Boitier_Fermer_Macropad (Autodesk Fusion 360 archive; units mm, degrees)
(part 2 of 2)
extrude "Extrusion20" add sketch "Esquisse6" profile of L6 L7 L8 L13 along normal blind 0.15
sketch "Esquisse7" plane through (0, -33.8138, 0) normal (0, 1, 0) x axis (-1, 0, 0)
  line L1 (51.5, 17.329) -> (51.5, 10.829)
  line L2 (40, 17.329) -> (51.5, 17.329)
  line L3 (40, 16.1066) -> (40, 17.329)
  line L4 (28, 16.1066) -> (40, 16.1066)
  line L5 (28, 17.329) -> (28, 16.1066)
  line L6 (-31.9217, 17.329) -> (28, 17.329)
  line L7 (-31.9217, 10.829) -> (-31.9217, 17.329)
  line L8 (51.5, 10.829) -> (-31.9217, 10.829)
  line L9 (29.5, 16.1066) -> (28, 16.1066)
  line L10 (29.5, 10.829) -> (29.5, 16.1066)
  line L11 (28, 10.829) -> (29.5, 10.829)
  line L12 (28, 16.1066) -> (28, 10.829)
  line L13 (38.5, 16.1066) -> (40, 16.1066)
  line L14 (38.5, 10.829) -> (38.5, 16.1066)
  line L15 (40, 10.829) -> (38.5, 10.829)
  line L16 (40, 16.1066) -> (40, 10.829)
  point P6 (28, 16.1066)
  point P10 (28, 16.1066)
  point P5 (40, 16.1066)
  point P14 (40, 16.1066)
  point P11 (29.5, 16.1066)
  point P15 (38.5, 16.1066)
  horizontal L9
  vertical L10
  horizontal L11
  vertical L12
  coincident P6 P10
  horizontal L13
  vertical L14
  horizontal L15
  vertical L16
  coincident P5 P14
  dimension "d115" distance P10 P11 = 1.5
  dimension "d116" distance P14 P15 = 1.5
extrude "Extrusion21" add sketch "Esquisse7" profile of L4 L8 L9 L10 L11 L12 L13 L14 L15 L16 along normal blind 62.447
revolve "Révolution1" AlongAngle 10
revolve "Révolution2" AlongAngle 10
sketch "Esquisse8" plane through (0, 28.6329, 0) normal (0, -1, 0) x axis (1, 0, 0)
  line L1 (-40, 16.1066) -> (-40, 10.829)
  line L2 (-38.5, 16.1066) -> (-40, 16.1066)
  line L3 (-38.5, 10.829) -> (-38.5, 16.1066)
  line L4 (-29.5, 10.829) -> (-38.5, 10.829)
  line L5 (-29.5, 16.1066) -> (-29.5, 10.829)
  line L6 (-28, 16.1066) -> (-29.5, 16.1066)
  line L7 (-28, 10.829) -> (-28, 16.1066)
  line L8 (54.6352, 10.829) -> (-28, 10.829)
  line L9 (54.6352, 27.384) -> (54.6352, 10.829)
  line L10 (-28, 27.384) -> (54.6352, 27.384)
  line L11 (-28, 27.1177) -> (-28, 27.384)
  line L12 (-40, 27.1177) -> (-28, 27.1177)
  line L13 (-40, 27.384) -> (-40, 27.1177)
  line L14 (-51.5, 27.384) -> (-40, 27.384)
  line L15 (-51.5, 10.829) -> (-51.5, 27.384)
  line L16 (-40, 10.829) -> (-51.5, 10.829)
  line L17 (-28, 26.9504) -> (-28, 16.1066)
  line L18 (-40, 26.9504) -> (-40, 16.1066)
  line L19 (-40, 27.1177) -> (-40, 26.9504)
  line L20 (-40, 27.384) -> (-40, 27.1177)
  line L21 (-38.5, 16.1066) -> (-40, 16.1066)
  line L22 (-38.5, 27.1177) -> (-38.5, 16.1066)
  line L23 (-40, 27.1177) -> (-38.5, 27.1177)
  line L24 (-40, 16.1066) -> (-40, 27.1177)
  line L25 (-28, 16.1066) -> (-29.5, 16.1066)
  line L26 (-28, 27.1177) -> (-28, 16.1066)
  line L27 (-29.5, 27.1177) -> (-28, 27.1177)
  line L28 (-29.5, 16.1066) -> (-29.5, 27.1177)
  point P26 (-38.5, 27.1177)
  point P20 (-40, 16.1066)
  point P24 (-40, 16.1066)
  point P13 (-28, 27.1177)
  point P30 (-28, 27.1177)
  point P7 (-29.5, 16.1066)
  point P28 (-29.5, 16.1066)
  point P25 (-38.5, 16.1066)
  horizontal L21
  vertical L22
  horizontal L23
  vertical L24
  coincident L12 P26
  coincident P20 P24
  horizontal L25
  vertical L26
  horizontal L27
  vertical L28
  coincident P13 P30
  coincident P7 P28
  dimension "d121" distance P24 P25 = 1.5
extrude "Extrusion22" add sketch "Esquisse8" profile of L2 L6 L12 L17 L18 L19 L21 L22 L23 L24 L25 L26 L27 L28 along normal blind 2
sketch "Esquisse1" plane through (0, 0, 10.829) normal (0, 0, -1) x axis (1, 0, 0)
  line L1 (-29.5, 33.8138) -> (-38.5, 33.8138)
  line L2 (-29.5, -28.6329) -> (-29.5, 33.8138)
  line L3 (-38.5, -28.6329) -> (-29.5, -28.6329)
  line L4 (-38.5, 33.8138) -> (-38.5, -28.6329)
  line L5 (-40, -28.6329) -> (-40, 33.8138)
  line L6 (-51.5, -28.6329) -> (-40, -28.6329)
  line L7 (-51.5, -24.5983) -> (-51.5, -28.6329)
  line L8 (-54, -22.1363) -> (-51.5, -24.5983)
  line L9 (-59.5673, -22.1363) -> (-54, -22.1363)
  line L10 (-59.5673, 25.627) -> (-59.5673, -22.1363)
  line L11 (-54, 25.627) -> (-59.5673, 25.627)
  line L12 (-51.5, 28.089) -> (-54, 25.627)
  line L13 (-51.5, 33.8138) -> (-51.5, 28.089)
  line L14 (-40, 33.8138) -> (-51.5, 33.8138)
  line L15 (31.9217, 33.8138) -> (-28, 33.8138)
  line L16 (34.6131, 29.5161) -> (31.9217, 33.8138)
  line L17 (52.9048, 29.5161) -> (34.6131, 29.5161)
  line L18 (54.6352, 32.6305) -> (52.9048, 29.5161)
  line L19 (54.6352, 28.6738) -> (54.6352, 32.6305)
  line L20 (53.7874, 27.1479) -> (54.6352, 28.6738)
  line L21 (54.6352, 25.627) -> (53.7874, 27.1479)
  line L22 (62.5975, 25.627) -> (54.6352, 25.627)
  line L23 (62.5975, -22.1363) -> (62.5975, 25.627)
  line L24 (57.1352, -22.1363) -> (62.5975, -22.1363)
  line L25 (54.6352, -24.5983) -> (57.1352, -22.1363)
  line L26 (54.6352, -28.6329) -> (54.6352, -24.5983)
  line L27 (-28, -28.6329) -> (54.6352, -28.6329)
  line L28 (-28, 33.8138) -> (-28, -28.6329)
  line L29 (61.6004, -30.3827) -> (-58.5552, -30.3827)
  line L30 (64.3975, -27.4794) -> (61.6004, -30.3827)
  line L31 (64.3975, 32.3196) -> (64.3975, -27.4794)
  line L32 (61.2304, 35.4386) -> (64.3975, 32.3196)
  line L33 (54.1497, 35.4386) -> (61.2304, 35.4386)
  line L34 (51.9955, 31.5614) -> (54.1497, 35.4386)
  line L35 (35.4395, 31.5614) -> (51.9955, 31.5614)
  line L36 (32.9332, 35.5637) -> (35.4395, 31.5614)
  line L37 (-58.5662, 35.5637) -> (32.9332, 35.5637)
  line L38 (-61.3673, 33.2697) -> (-58.5662, 35.5637)
  line L39 (-61.3673, -27.4752) -> (-61.3673, 33.2697)
  line L40 (-58.5552, -30.3827) -> (-61.3673, -27.4752)
  line L41 (-51.3, -28.4329) -> (-40.2, -28.4329)
  line L42 (-51.3, -24.5146) -> (-51.3, -28.4329)
  line L43 (-53.9181, -21.9363) -> (-51.3, -24.5146)
  line L44 (-59.3673, -21.9363) -> (-53.9181, -21.9363)
  line L45 (-59.3673, 25.427) -> (-59.3673, -21.9363)
  line L46 (-53.9181, 25.427) -> (-59.3673, 25.427)
  line L47 (-51.3, 28.0053) -> (-53.9181, 25.427)
  line L48 (-51.3, 33.6138) -> (-51.3, 28.0053)
  line L49 (-40.2, 33.6138) -> (-51.3, 33.6138)
  line L50 (-40.2, -28.4329) -> (-40.2, 33.6138)
  line L51 (62.3975, 25.427) -> (54.5177, 25.427)
  line L52 (62.3975, -21.9363) -> (62.3975, 25.427)
  line L53 (57.0533, -21.9363) -> (62.3975, -21.9363)
  line L54 (54.4352, -24.5146) -> (57.0533, -21.9363)
  line L55 (54.4352, -28.4329) -> (54.4352, -24.5146)
  line L56 (-27.8, -28.4329) -> (54.4352, -28.4329)
  line L57 (-27.8, 33.6138) -> (-27.8, -28.4329)
  line L58 (31.811, 33.6138) -> (-27.8, 33.6138)
  line L59 (34.5023, 29.3161) -> (31.811, 33.6138)
  line L60 (-48.52, -23.3506) -> (-48.52, -25.6529)
  line L61 (-52.779, -19.1563) -> (-48.52, -23.3506)
  line L62 (-56.5873, -19.1563) -> (-52.779, -19.1563)
  line L63 (-56.5873, 22.647) -> (-56.5873, -19.1563)
  line L64 (-52.779, 22.647) -> (-56.5873, 22.647)
  line L65 (-48.52, 26.8413) -> (-52.779, 22.647)
  line L66 (-48.52, 30.8338) -> (-48.52, 26.8413)
  line L67 (-42.98, 30.8338) -> (-48.52, 30.8338)
  line L68 (-42.98, -25.6529) -> (-42.98, 30.8338)
  line L69 (-48.52, -25.6529) -> (-42.98, -25.6529)
  line L70 (52.3496, 29.3161) -> (54.5177, 25.427)
  line L71 (34.5023, 29.3161) -> (52.3496, 29.3161)
  line L72 (52.8847, 22.647) -> (50.7166, 26.5361)
  line L73 (59.6175, 22.647) -> (52.8847, 22.647)
  line L74 (59.6175, -19.1563) -> (59.6175, 22.647)
  line L75 (55.9142, -19.1563) -> (59.6175, -19.1563)
  line L76 (51.6552, -23.3506) -> (55.9142, -19.1563)
  line L77 (51.6552, -25.6529) -> (51.6552, -23.3506)
  line L78 (-25.02, -25.6529) -> (51.6552, -25.6529)
  line L79 (-25.02, 30.8338) -> (-25.02, -25.6529)
  line L80 (30.2718, 30.8338) -> (-25.02, 30.8338)
  line L81 (32.9631, 26.5361) -> (30.2718, 30.8338)
  line L82 (50.7166, 26.5361) -> (32.9631, 26.5361)
  line L83 (-25.02, -28.4329) -> (-25.02, -25.6529)
  line L84 (-25.02, 33.6138) -> (-25.02, 30.8338)
  line L85 (-42.98, 33.6138) -> (-42.98, 30.8338)
  line L86 (-42.98, -28.4329) -> (-42.98, -25.6529)
  point P84 (-25.02, -28.4329)
  point P85 (-25.02, 33.6138)
  point P86 (-42.98, 33.6138)
  point P87 (-42.98, -28.4329)
  horizontal L71
  coincident L56 P84
  perpendicular L56 L83
  coincident L58 P85
  perpendicular L58 L84
  coincident L49 P86
  perpendicular L49 L85
  coincident L41 P87
  perpendicular L41 L86
  dimension "d124" = 0.2
  dimension "d125" = 0.2
  dimension "d126" = 2.98 (= "3 mm - 0.02 mm")
  dimension "d127" = 2.98
extrude "Extrusion1" new body sketch "Esquisse1" profile of L44 L46 L48 L41 L43 L47 L45 L42 L49 L55 L51 L53 L52 L54 L56 L59 L58 L66 L69 L61 L60 L65 L63 L62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 against normal blind 3
sketch "Esquisse2" plane through (0, 0, 10.829) normal (0, 0, -1) x axis (1, 0, 0)
  line L1 (-29.5, 33.8138) -> (-38.5, 33.8138)
  line L2 (-29.5, -28.6329) -> (-29.5, 33.8138)
  line L3 (-38.5, -28.6329) -> (-29.5, -28.6329)
  line L4 (-38.5, 33.8138) -> (-38.5, -28.6329)
  line L5 (-40, -28.6329) -> (-40, 33.8138)
  line L6 (-51.5, -28.6329) -> (-40, -28.6329)
  line L7 (-51.5, -24.5983) -> (-51.5, -28.6329)
  line L8 (-54, -22.1363) -> (-51.5, -24.5983)
  line L9 (-59.5673, -22.1363) -> (-54, -22.1363)
  line L10 (-59.5673, 25.627) -> (-59.5673, -22.1363)
  line L11 (-54, 25.627) -> (-59.5673, 25.627)
  line L12 (-51.5, 28.089) -> (-54, 25.627)
  line L13 (-51.5, 33.8138) -> (-51.5, 28.089)
  line L14 (-40, 33.8138) -> (-51.5, 33.8138)
  line L15 (31.9217, 33.8138) -> (-28, 33.8138)
  line L16 (34.6131, 29.5161) -> (31.9217, 33.8138)
  line L17 (52.9048, 29.5161) -> (34.6131, 29.5161)
  line L18 (54.6352, 32.6305) -> (52.9048, 29.5161)
  line L19 (54.6352, 28.6738) -> (54.6352, 32.6305)
  line L20 (53.7874, 27.1479) -> (54.6352, 28.6738)
  line L21 (54.6352, 25.627) -> (53.7874, 27.1479)
  line L22 (62.5975, 25.627) -> (54.6352, 25.627)
  line L23 (62.5975, -22.1363) -> (62.5975, 25.627)
  line L24 (57.1352, -22.1363) -> (62.5975, -22.1363)
  line L25 (54.6352, -24.5983) -> (57.1352, -22.1363)
  line L26 (54.6352, -28.6329) -> (54.6352, -24.5983)
  line L27 (-28, -28.6329) -> (54.6352, -28.6329)
  line L28 (-28, 33.8138) -> (-28, -28.6329)
  line L29 (61.6004, -30.3827) -> (-58.5552, -30.3827)
  line L30 (64.3975, -27.4794) -> (61.6004, -30.3827)
  line L31 (64.3975, 32.3196) -> (64.3975, -27.4794)
  line L32 (61.2304, 35.4386) -> (64.3975, 32.3196)
  line L33 (54.1497, 35.4386) -> (61.2304, 35.4386)
  line L34 (51.9955, 31.5614) -> (54.1497, 35.4386)
  line L35 (35.4395, 31.5614) -> (51.9955, 31.5614)
  line L36 (32.9332, 35.5637) -> (35.4395, 31.5614)
  line L37 (-58.5662, 35.5637) -> (32.9332, 35.5637)
  line L38 (-61.3673, 33.2697) -> (-58.5662, 35.5637)
  line L39 (-61.3673, -27.4752) -> (-61.3673, 33.2697)
  line L40 (-58.5552, -30.3827) -> (-61.3673, -27.4752)
extrude "Extrusion2" add sketch "Esquisse2" along normal blind 2
work_plane "Plan de construction2"
sketch "Esquisse14" plane through (0, -97.5905, 0) normal (0, -1, 0) x axis (-1, 0, 0)
  line L1 (-117.5975, -10.829) -> (-117.5975, -22.9259)
  line L2 (-117.5975, -14.5039) -> (-117.5975, -10.829)
  line L3 (-117.5975, -17.9507) -> (-117.5975, -14.5039)
  line L4 (-117.5975, -26.3727) -> (-117.5975, -17.9507)
  line L5 (-117.5975, -22.9259) -> (-117.5975, -26.3727)
  line L6 (-116.0033, -15.6973) -> (-117.5975, -14.1031)
  line L7 (-115.343, -14.1031) -> (-117.5975, -14.1031)
  line L8 (-116.0033, -18.5) -> (-116.0033, -15.6973)
  line L9 (-117.5975, -18.5) -> (-116.0033, -18.5)
  point P7 (-117.5975, -14.1031)
  point P11 (-117.5975, -18.5)
  horizontal L7
  coincident L2 P7
  parallel L3 L8
  coincident L4 P11
  dimension "d132" angle L6 L7 = 45
  dimension "d133" angle L8 L9 = 90
extrude "Extrusion23" add sketch "Esquisse14" profile of L1 L2 L3 L4 L6 L8 L9 distance 6
extrude "Extrusion24" add of existing geometry blind 2
sketch "Esquisse15" plane through (116.0033, 0, 0) normal (-1, 0, 0) x axis (0, -1, 0)
  line L1 (103.5905, 15.6973) -> (91.5905, 15.6973)
  line L2 (103.5905, 20.5) -> (103.5905, 15.6973)
  line L3 (91.5905, 20.5) -> (103.5905, 20.5)
  line L4 (91.5905, 15.6973) -> (91.5905, 20.5)
  line L5 (102.5905, 16.6973) -> (92.5905, 16.6973)
  line L6 (102.5905, 19.5) -> (102.5905, 16.6973)
  line L7 (92.5905, 19.5) -> (102.5905, 19.5)
  line L8 (92.5905, 16.6973) -> (92.5905, 19.5)
  dimension "d138" = -1
extrude "Extrusion25" cut sketch "Esquisse15" profile of L7 L5 L6 L8 against normal blind 1.594
chamfer "Chanfrein4" distance 1.59 distance 1
work_plane "Plan de construction3"
mirror "Symétrie miroir1" mirrorStitchTolerance 0.1
sketch "Esquisse3" plane through (0, -2.5905, 0) normal (0, -1, 0) x axis (-1, 0, 0)
  line L1 (-59.6175, -13.829) -> (-59.6175, -10.829)
  line L2 (-59.6175, -10.829) -> (-59.6175, -13.829)
  line L3 (-30.2718, -13.829) -> (-32.9631, -13.829)
  line L4 (25.02, -13.829) -> (-30.2718, -13.829)
  line L5 (-51.6552, -13.829) -> (25.02, -13.829)
  line L6 (-55.9142, -13.829) -> (-51.6552, -13.829)
  line L7 (-50.7166, -13.829) -> (-52.8847, -13.829)
  line L8 (-32.9631, -13.829) -> (-50.7166, -13.829)
  line L9 (-54.5177, -13.829) -> (-52.3496, -13.829)
  line L10 (-62.3975, -13.829) -> (-54.5177, -13.829)
  line L11 (-54.4352, -13.829) -> (-57.0533, -13.829)
  line L12 (25.02, -13.829) -> (-54.4352, -13.829)
  line L13 (-31.811, -13.829) -> (25.02, -13.829)
  line L14 (-34.5023, -13.829) -> (-31.811, -13.829)
  line L15 (-52.3496, -13.829) -> (-34.5023, -13.829)
  line L16 (-50.7166, -10.829) -> (-32.9631, -10.829)
  line L17 (-52.8847, -10.829) -> (-50.7166, -10.829)
  line L18 (-59.6175, -10.829) -> (-52.8847, -10.829)
  line L19 (-55.9142, -10.829) -> (-59.6175, -10.829)
  line L20 (-51.6552, -10.829) -> (-55.9142, -10.829)
  line L21 (25.02, -10.829) -> (-51.6552, -10.829)
  line L22 (-30.2718, -10.829) -> (25.02, -10.829)
  line L23 (-32.9631, -10.829) -> (-30.2718, -10.829)
  line L24 (-62.5973, -18.5) -> (-62.5973, -17.6973)
  line L25 (-62.5973, -17.6973) -> (-62.5973, -18.5)
  line L26 (-61.0073, -16.6973) -> (-62.5973, -17.6973)
  line L27 (-62.5973, -17.6973) -> (-61.0073, -16.6973)
  line L28 (-62.5973, -18.5) -> (-61.0073, -19.5)
  line L29 (-61.0073, -19.5) -> (-62.5973, -18.5)
  line L30 (-62.5973, -17.6973) -> (-61.0073, -16.6973)
  line L31 (-62.5973, -18.5) -> (-62.5973, -17.6973)
  line L32 (-61.0073, -19.5) -> (-62.5973, -18.5)
  line L33 (-61.0033, -15.6973) -> (-62.5975, -14.1031)
  line L34 (-62.5975, -14.1031) -> (-61.0033, -15.6973)
  line L35 (-62.4473, -18.4418) -> (-61.0033, -19.35)
  line L36 (-62.4473, -17.7652) -> (-62.4473, -18.4418)
  line L37 (-61.0033, -16.857) -> (-62.4473, -17.7652)
  line L38 (-61.0033, -16.857) -> (-60.903, -16.7939)
  line L39 (-60.903, -19.4131) -> (-61.0033, -19.35)
  line L40 (-58.403, -19.4131) -> (-60.903, -19.4131)
  line L41 (-58.403, -10.829) -> (-58.403, -19.4131)
  line L42 (-60.903, -13.829) -> (-60.903, -16.7939)
  line L43 (52.779, -10.829) -> (48.52, -10.829)
  line L44 (56.5873, -10.829) -> (52.779, -10.829)
  line L45 (52.779, -10.829) -> (56.5873, -10.829)
  line L46 (48.52, -10.829) -> (52.779, -10.829)
  line L47 (42.98, -10.829) -> (48.52, -10.829)
  line L48 (51.3, -10.829) -> (42.98, -10.829)
  line L49 (53.9181, -10.829) -> (51.3, -10.829)
  line L50 (59.3673, -10.829) -> (53.9181, -10.829)
  line L51 (53.9181, -10.829) -> (59.3673, -10.829)
  line L52 (51.3, -10.829) -> (53.9181, -10.829)
  line L53 (42.98, -10.829) -> (51.3, -10.829)
  line L54 (48.52, -10.829) -> (42.98, -10.829)
  line L55 (-54.4352, -10.829) -> (25.02, -10.829)
  line L56 (-57.0533, -10.829) -> (-54.4352, -10.829)
  line L57 (-62.3975, -10.829) -> (-57.0533, -10.829)
  line L58 (-54.5177, -10.829) -> (-62.3975, -10.829)
  line L59 (-52.3496, -10.829) -> (-54.5177, -10.829)
  line L60 (-34.5023, -10.829) -> (-52.3496, -10.829)
  line L61 (-31.811, -10.829) -> (-34.5023, -10.829)
  line L62 (25.02, -10.829) -> (-31.811, -10.829)
  line L63 (61.3673, -10.829) -> (58.5552, -10.829)
  line L64 (58.5662, -10.829) -> (61.3673, -10.829)
  line L65 (-32.9332, -10.829) -> (58.5662, -10.829)
  line L66 (-35.4395, -10.829) -> (-32.9332, -10.829)
  line L67 (-51.9955, -10.829) -> (-35.4395, -10.829)
  line L68 (-54.1497, -10.829) -> (-51.9955, -10.829)
  line L69 (-61.2304, -10.829) -> (-54.1497, -10.829)
  line L70 (-64.3975, -10.829) -> (-61.2304, -10.829)
  line L71 (-61.6004, -10.829) -> (-64.3975, -10.829)
  line L72 (58.5552, -10.829) -> (-61.6004, -10.829)
  point P46 (-58.403, -10.829)
  point P44 (-60.903, -19.4131)
  point P45 (-58.403, -19.4131)
  parallel L32 L35
  parallel L27 L37
  parallel L37 L38
  coincident L19 P46
  vertical L42
  dimension "d145" distance L24 L36 = 0.15
  dimension "d146" distance P44 P45 = 2.5
  dimension "d147" angle L40 L41 = 90
extrude "Extrusion3" add sketch "Esquisse3" profile of L1 L2 L10 L18 L19 L35 L36 L37 L38 L39 L40 L41 L42 distance 5
chamfer "Chanfrein1" distance 1.5
fillet "Congé2" radius 1
mirror "Symétrie miroir1" mirrorStitchTolerance 0.1
offset_faces "DécalerLesFaces" distance 0.1
sketch "Esquisse9" plane through (-28, 0, 0) normal (1, 0, 0) x axis (0, 1, 0)
  line L1 (28.6329, 27.384) -> (28.6329, 10.829)
  line L2 (27.1329, 28.884) -> (28.6329, 27.384)
  line L3 (26.7856, 30.8537) -> (27.1329, 28.884)
  line L4 (-32.6611, 20.3716) -> (26.7856, 30.8537)
  line L5 (-32.3778, 18.765) -> (-32.6611, 20.3716)
  line L6 (-33.8138, 17.329) -> (-32.3778, 18.765)
  line L7 (-33.8138, 10.829) -> (-33.8138, 17.329)
  line L8 (28.6329, 10.829) -> (-33.8138, 10.829)
  line L9 (25.6529, 13.829) -> (25.6529, 12.829)
  line L10 (25.6529, 10.829) -> (25.6529, 12.829)
  line L11 (25.6529, 13.829) -> (25.6529, 10.829)
  line L12 (-22.647, 10.829) -> (-7.5905, 10.829)
  line L13 (-26.8413, 10.829) -> (-22.647, 10.829)
  line L14 (-30.8338, 10.829) -> (-26.8413, 10.829)
  line L15 (-32.6138, 10.829) -> (-30.8338, 10.829)
  line L16 (-33.6138, 10.829) -> (-32.6138, 10.829)
  line L17 (-28.0053, 10.829) -> (-33.6138, 10.829)
  line L18 (-25.427, 10.829) -> (-28.0053, 10.829)
  line L19 (21.9363, 10.829) -> (-25.427, 10.829)
  line L20 (24.5146, 10.829) -> (21.9363, 10.829)
  line L21 (28.4329, 10.829) -> (24.5146, 10.829)
  line L22 (27.4329, 10.829) -> (28.4329, 10.829)
  line L23 (25.6529, 10.829) -> (27.4329, 10.829)
  line L24 (23.3506, 10.829) -> (25.6529, 10.829)
  line L25 (19.1563, 10.829) -> (23.3506, 10.829)
  line L26 (2.4095, 10.829) -> (19.1563, 10.829)
  line L27 (-7.5905, 10.829) -> (2.4095, 10.829)
  line L28 (27.4752, 10.829) -> (30.3827, 10.829)
  line L29 (-33.2697, 10.829) -> (27.4752, 10.829)
  line L30 (-35.5637, 10.829) -> (-33.2697, 10.829)
  line L31 (-31.5614, 10.829) -> (-35.5637, 10.829)
  line L32 (-35.4386, 10.829) -> (-31.5614, 10.829)
  line L33 (-32.3196, 10.829) -> (-35.4386, 10.829)
  line L34 (27.4794, 10.829) -> (-32.3196, 10.829)
  line L35 (30.3827, 10.829) -> (27.4794, 10.829)
  line L36 (2.4095, 10.829) -> (-7.5905, 10.829)
  line L37 (19.1563, 10.829) -> (2.4095, 10.829)
  line L38 (23.3506, 10.829) -> (19.1563, 10.829)
  line L39 (25.6529, 10.829) -> (23.3506, 10.829)
  line L40 (27.4329, 10.829) -> (25.6529, 10.829)
  line L41 (27.4329, 10.829) -> (28.4329, 10.829)
  line L42 (24.5146, 10.829) -> (28.4329, 10.829)
  line L43 (21.9363, 10.829) -> (24.5146, 10.829)
  line L44 (-25.427, 10.829) -> (21.9363, 10.829)
  line L45 (-29.3161, 10.829) -> (-25.427, 10.829)
  line L46 (-33.6138, 10.829) -> (-29.3161, 10.829)
  line L47 (-33.6138, 10.829) -> (-32.6138, 10.829)
  line L48 (-30.8338, 10.829) -> (-32.6138, 10.829)
  line L49 (-26.5361, 10.829) -> (-30.8338, 10.829)
  line L50 (-22.647, 10.829) -> (-26.5361, 10.829)
  line L51 (-7.5905, 10.829) -> (-22.647, 10.829)
  line L52 (-30.8338, 12.829) -> (-30.8338, 13.829)
  line L53 (-30.8338, 10.829) -> (-30.8338, 13.829)
  line L54 (-30.8338, 12.829) -> (-30.8338, 10.829)
  line L55 (23.6329, 10.829) -> (23.6329, 15)
  line L56 (28.6329, 17) -> (25.6329, 17)
  arc A1 centre (25.6329, 15) radius 2 clockwise from (23.6329, 15) to (25.6329, 17)
  point P42 (23.6329, 10.829)
  point P43 (28.6329, 17)
  vertical L55
  coincident L21 P42
  coincident L1 P43
  perpendicular L1 L56
  tangent L56 A1
  tangent L55 A1
  dimension "d159" distance L1 L55 = 5
  dimension "d160" radius A1 = 2
extrude "Extrusion26" cut sketch "Esquisse9" profile of L1 L8 L20 L21 L22 L23 L24 L28 L29 L34 L35 L39 L40 L41 L42 L43 L55 L56 A1 against normal blind 12
fillet "Congé3" radius 3
fillet "Congé4" radius 2
chamfer "Chanfrein2" distance 1.5
sketch "Esquisse16" plane through (0, -7.3332, 41.5887) normal (0, -0.1736, 0.9848) x axis (1, 0, 0)
  line L1 (109.6352, -61.8204) -> (27, -61.8204)
  line L2 (109.6352, -65.2757) -> (109.6352, -61.8204)
  line L3 (112.1352, -67.7757) -> (109.6352, -65.2757)
  line L4 (116.0975, -67.7757) -> (112.1352, -67.7757)
  line L5 (116.0975, -116.2758) -> (116.0975, -67.7757)
  line L6 (109.6352, -116.2758) -> (116.0975, -116.2758)
  line L7 (108.7874, -117.8201) -> (109.6352, -116.2758)
  line L8 (88.7826, -117.8201) -> (108.7874, -117.8201)
  line L9 (86.0912, -122.1841) -> (88.7826, -117.8201)
  line L10 (27, -122.1841) -> (86.0912, -122.1841)
  line L11 (27, -61.8204) -> (27, -122.1841)
  line L12 (24.5927, -72.9304) -> (24.5927, -65.4304)
  line L13 (17.4927, -78.5504) -> (24.5927, -72.9304)
  line L14 (17.4927, -71.0504) -> (17.4927, -78.5504)
  line L15 (24.5927, -65.4304) -> (17.4927, -71.0504)
  line L16 (24.5927, -111.5304) -> (24.5927, -104.0304)
  line L17 (17.4927, -117.1504) -> (24.5927, -111.5304)
  line L18 (17.4927, -109.6504) -> (17.4927, -117.1504)
  line L19 (24.5927, -104.0304) -> (17.4927, -109.6504)
  line L20 (24.5927, -92.5304) -> (24.5927, -85.0304)
  line L21 (17.4927, -98.1504) -> (24.5927, -92.5304)
  line L22 (17.4927, -90.6504) -> (17.4927, -98.1504)
  line L23 (24.5927, -85.0304) -> (17.4927, -90.6504)
  line L24 (-3.0838, -59.6204) -> (116.1277, -59.6204)
  line L25 (-5.2673, -61.9129) -> (-3.0838, -59.6204)
  line L26 (-5.2673, -122.6389) -> (-5.2673, -61.9129)
  line L27 (-3.1686, -124.3841) -> (-5.2673, -122.6389)
  line L28 (87.3192, -124.3841) -> (-3.1686, -124.3841)
  line L29 (90.0105, -120.0201) -> (87.3192, -124.3841)
  line L30 (107.7872, -120.0201) -> (90.0105, -120.0201)
  line L31 (109.8056, -124.2571) -> (107.7872, -120.0201)
  line L32 (115.7748, -124.2571) -> (109.8056, -124.2571)
  line L33 (118.2975, -121.7344) -> (115.7748, -124.2571)
  line L34 (118.2975, -61.9073) -> (118.2975, -121.7344)
  line L35 (116.1277, -59.6204) -> (118.2975, -61.9073)
  line L36 (15, -122.1841) -> (15, -61.8204)
  line L37 (3.5, -122.1841) -> (15, -122.1841)
  line L38 (3.5, -118.7758) -> (3.5, -122.1841)
  line L39 (1, -116.2758) -> (3.5, -118.7758)
  line L40 (-3.0673, -116.2758) -> (1, -116.2758)
  line L41 (-3.0673, -67.7757) -> (-3.0673, -116.2758)
  line L42 (1, -67.7757) -> (-3.0673, -67.7757)
  line L43 (3.5, -65.2757) -> (1, -67.7757)
  line L44 (3.5, -61.8204) -> (3.5, -65.2757)
  line L45 (15, -61.8204) -> (3.5, -61.8204)
  line L46 (109.6352, -59.6204) -> (109.6352, -61.8204)
  line L47 (107.1352, -59.6204) -> (109.6352, -59.6204)
  line L48 (106.1192, -59.6204) -> (107.1352, -59.6204)
  line L49 (92.4272, -59.6204) -> (106.6272, -59.6204)
  line L50 (92.9352, -59.6204) -> (92.4272, -59.6204)
  line L51 (91.9192, -59.6204) -> (92.4272, -59.6204)
  line L52 (107.6352, -61.8204) -> (105.6192, -61.8204)
  line L53 (107.6352, -59.6204) -> (107.6352, -61.8204)
  line L54 (105.6192, -59.6204) -> (107.6352, -59.6204)
  line L55 (105.6192, -61.8204) -> (105.6192, -59.6204)
  line L56 (93.4352, -61.8204) -> (91.4192, -61.8204)
  line L57 (93.4352, -59.6204) -> (93.4352, -61.8204)
  line L58 (91.4192, -59.6204) -> (93.4352, -59.6204)
  line L59 (91.4192, -61.8204) -> (91.4192, -59.6204)
  circle C1 centre (-0.5, -120.2758) radius 1.5
  circle C2 centre (-0.5, -63.7757) radius 1.5
  circle C3 centre (113.6352, -120.2758) radius 1.5
  circle C4 centre (113.6352, -63.7757) radius 1.5
  point P3 (109.6352, -61.8204)
  point P51 (109.6352, -61.8204)
  point P52 (109.6352, -59.6204)
  point P55 (106.6272, -59.6204)
  point P61 (107.6352, -59.6204)
  point P59 (105.6192, -61.8204)
  point P65 (93.4352, -59.6204)
  point P63 (91.4192, -61.8204)
  point P53 (107.1352, -59.6204)
  point P54 (106.1192, -59.6204)
  point P56 (92.4272, -59.6204)
  point P57 (92.9352, -59.6204)
  point P58 (91.9192, -59.6204)
  coincident P3 P51
  coincident L24 P52
  perpendicular L24 L46
  perpendicular L46 L47
  parallel L24 L48
  midpoint L48 P55
  parallel L24 L49
  parallel L24 L50
  parallel L24 L51
  horizontal L52
  vertical L53
  horizontal L54
  vertical L55
  coincident L24 P61
  coincident L1 P59
  horizontal L56
  vertical L57
  horizontal L58
  vertical L59
  coincident L49 P65
  coincident L1 P63
  dimension "d168" distance P52 P53 = 2.5
  dimension "d169" distance P53 P54 = 1.016
  dimension "d170" distance P55 P56 = 14.2
  dimension "d171" distance P56 P57 = 0.508 (= "1.016 mm / 2")
  dimension "d172" distance P56 P58 = 0.508 (= "1.016 mm / 2")
  dimension "d173" distance P54 L55 = 0.5
  dimension "d174" distance P53 L53 = 0.5
  dimension "d175" distance P58 L59 = 0.5
  dimension "d176" distance P57 L57 = 0.5
extrude "Extrusion27" cut sketch "Esquisse16" profile of L1 L24 L52 L53 L54 L55 L56 L57 L58 L59 against normal blind 4
chamfer "Chanfrein5" distance 1
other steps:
create_component "CreateComponent1"
create_component "CreateComponent2"
create_component "CreateComponent4"

design "PCB5_Complex_Finale_Design"
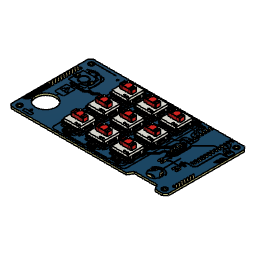
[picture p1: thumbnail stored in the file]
description: Designed by EasyEDA Pro
part number: EasyEDA PCB Model~p9xJ
description: Part Number
part number: Board~p9xJ
part number: TopCopper~p9xJ
part number: BottomCopper~p9xJ
part number: TopSilkscreen~p9xJ
part number: BottomSilkscreen~p9xJ
part number: SMA_L4.4-W2.8-LS5.4-RD~SMA_L4.4-W2.8-LS5.4-RD~p9xJ
part number: D1~SMA_L4.4-W2.8-LS5.4-RD~SMA_L4.4-W2.8-LS5.4-RD~p9xJ
part number: KEY-TH_CPG135001D0X~KEY-TH_CPG135001D0X~p9xJ
part number: SW9~KEY-TH_CPG135001D0X~KEY-TH_CPG135001D0X~p9xJ
base_feature "Base Feature1"
base_feature "Base Feature1"
base_feature "Base Feature1"
base_feature "Base Feature1"
base_feature "Base Feature1"
base_feature "Base Feature1"
base_feature "Base Feature1"
base_feature "Base Feature1"
base_feature "Base Feature1"
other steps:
create_component "CreateComponent1"
create_component "CreateComponent2"
create_component "CreateComponent3"
create_component "CreateComponent4"
create_component "CreateComponent5"
create_component "CreateComponent6"
create_component "CreateComponent1"
create_component "CreateComponent7"
create_component "CreateComponent1"
create_component "CreateComponent8"
create_component "CreateComponent1"
create_component "CreateComponent9"
create_component "CreateComponent1"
